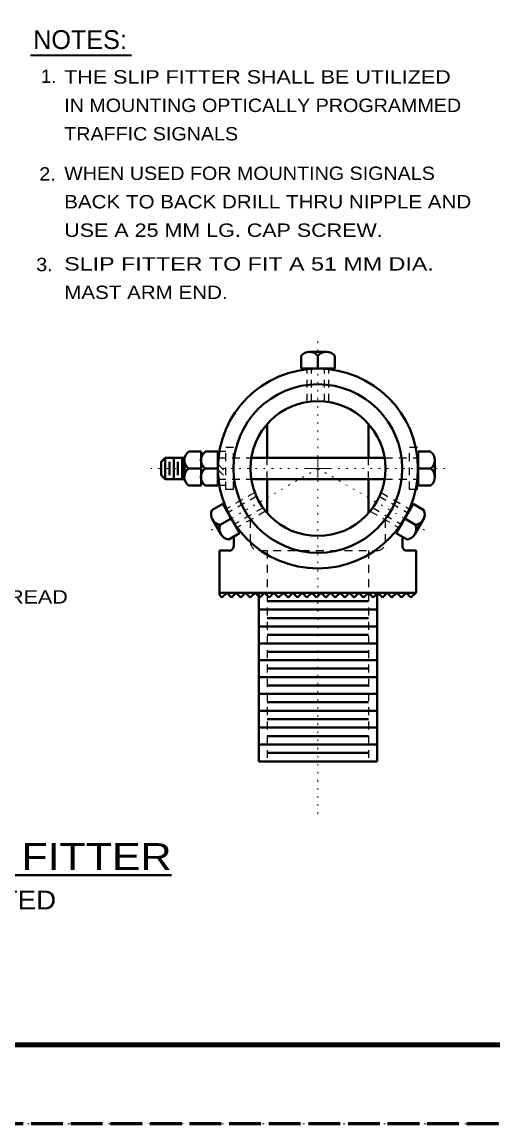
# Model space of a CAD drawing. Extents: x 312583 to 312854, y 144419 to 144597.
# Drawn here: x 312772.9 to 312799.7, y 144418.6 to 144481.2 of the extents above; entities that cross this region are included whole.
import ezdxf
from ezdxf.enums import TextEntityAlignment as Align

# ---------------------------------------------------------------- set-up
doc = ezdxf.new("R2010")
doc.units = 0
doc.header["$LTSCALE"] = 0.3
for name, pattern in [('DOTTED', [1.5, 0.3, -1.2]), ('LONG_DASHED', [7.5, 6, -1.5]), ('SHORT_DASHED', [2.7, 1.5, -1.2])]:
    doc.linetypes.add(name, pattern=pattern)
for name, color, linetype, lineweight in [('1', 7, 'Continuous', 40), ('2', 7, 'Continuous', 13), ('62', 7, 'DOTTED', 13), ('63', 7, 'LONG_DASHED', 60)]:
    doc.layers.add(name, color=color, linetype=linetype, lineweight=lineweight)

msp = doc.modelspace()

# ---------------------------------------------------------------- linework, layer by layer
at = {"layer": '1'}
for p, q in [((312788.779, 144462.2559), (312788.779, 144461.5429)), ((312790.2356, 144462.4935), (312789.239, 144462.4935)), ((312790.2203, 144462.4935), (312789.2466, 144462.4935)), ((312789.7373, 144462.2559), (312789.7373, 144461.5429)), ((312790.6956, 144462.2559), (312790.6956, 144461.5429)), ((312790.6956, 144461.5429), (312788.779, 144461.5429)), ((312786.8623, 144456.4675), (312786.8623, 144458.3842)), ((312792.6123, 144456.4675), (312792.6123, 144458.3842)), ((312782.385, 144456.8125), (312783.098, 144456.8125)), ((312783.098, 144454.8959), (312783.098, 144456.8125)), ((312783.3356, 144456.8125), (312784.0486, 144456.8125)), ((312784.0486, 144454.8959), (312784.0486, 144456.8125)), ((312796.1466, 144456.8125), (312795.4336, 144456.8125)), ((312795.4336, 144454.8959), (312795.4336, 144456.8125)), ((312781.0663, 144456.4675), (312782.1626, 144456.4675)), ((312781.3116, 144455.4785), (312781.3116, 144456.2299)), ((312781.5493, 144455.2409), (312781.5493, 144456.4675)), ((312781.787, 144455.4785), (312781.787, 144456.2299)), ((312782.0246, 144455.2409), (312782.0246, 144456.4675)), ((312782.155, 144455.3712), (312782.155, 144456.3449)), ((312783.098, 144455.3712), (312783.098, 144456.3449)), ((312785.9576, 144456.4675), (312793.5246, 144456.4675)), ((312796.3766, 144455.3559), (312796.3766, 144456.3525)), ((312796.3766, 144455.3712), (312796.3766, 144456.3449)), ((312782.385, 144455.8542), (312783.098, 144455.8542)), ((312783.3356, 144455.8542), (312784.0486, 144455.8542)), ((312796.1466, 144455.8542), (312795.4336, 144455.8542)), ((312781.0663, 144455.2409), (312782.1626, 144455.2409)), ((312782.385, 144454.8959), (312783.098, 144454.8959)), ((312783.3356, 144454.8959), (312784.0486, 144454.8959)), ((312785.9576, 144455.2409), (312793.5246, 144455.2409)), ((312786.8623, 144453.3165), (312786.8623, 144455.2409)), ((312792.6123, 144453.3165), (312792.6123, 144455.2409)), ((312796.1466, 144454.8959), (312795.4336, 144454.8959)), ((312783.7113, 144453.4775), (312784.3323, 144453.8379)), ((312784.3323, 144453.8379), (312785.2906, 144452.1742)), ((312794.1916, 144452.1742), (312795.15, 144453.8379)), ((312795.7633, 144453.4775), (312795.15, 144453.8379)), ((312783.742, 144452.9639), (312784.2403, 144452.0975)), ((312783.7496, 144452.9485), (312784.2403, 144452.1052)), ((312784.1943, 144452.6495), (312784.8076, 144453.0099)), ((312795.288, 144452.6495), (312794.667, 144453.0022)), ((312795.242, 144452.1052), (312795.7403, 144452.9715)), ((312795.2496, 144452.1205), (312795.7326, 144452.9639)), ((312784.6696, 144451.8215), (312785.2906, 144452.1742)), ((312794.805, 144451.8215), (312794.1916, 144452.1742)), ((312784.9533, 144451.4152), (312784.9533, 144451.9825)), ((312794.5443, 144451.4229), (312794.5443, 144451.9672)), ((312784.1406, 144451.1852), (312784.708, 144451.1852)), ((312795.311, 144451.1852), (312794.782, 144451.1852)), ((312784.1406, 144448.6629), (312784.2863, 144448.5172)), ((312784.5546, 144448.7855), (312784.2863, 144448.5172)), ((312784.5546, 144448.7855), (312784.823, 144448.5172)), ((312785.0913, 144448.7855), (312784.823, 144448.5172)), ((312785.0913, 144448.7855), (312785.3596, 144448.5172)), ((312785.628, 144448.7855), (312785.3596, 144448.5172)), ((312785.628, 144448.7855), (312785.8963, 144448.5172)), ((312786.1646, 144448.7855), (312785.8963, 144448.5172)), ((312786.1646, 144448.7855), (312786.433, 144448.5172)), ((312786.7013, 144448.7855), (312786.433, 144448.5172)), ((312786.7013, 144448.7855), (312786.9696, 144448.5172)), ((312787.238, 144448.7855), (312786.9696, 144448.5172)), ((312787.238, 144448.7855), (312787.5063, 144448.5172)), ((312787.7746, 144448.7855), (312787.5063, 144448.5172)), ((312787.7746, 144448.7855), (312788.043, 144448.5172)), ((312788.3113, 144448.7855), (312788.043, 144448.5172)), ((312788.3113, 144448.7855), (312788.5796, 144448.5172)), ((312788.848, 144448.7855), (312788.5796, 144448.5172)), ((312788.848, 144448.7855), (312789.1163, 144448.5172)), ((312789.3846, 144448.7855), (312789.1163, 144448.5172)), ((312789.3846, 144448.7855), (312789.653, 144448.5172)), ((312789.9213, 144448.7855), (312789.653, 144448.5172)), ((312789.9213, 144448.7855), (312790.1896, 144448.5172)), ((312790.458, 144448.7855), (312790.1896, 144448.5172)), ((312790.458, 144448.7855), (312790.7263, 144448.5172)), ((312790.9946, 144448.7855), (312790.7263, 144448.5172)), ((312790.9946, 144448.7855), (312791.263, 144448.5172)), ((312791.5313, 144448.7855), (312791.263, 144448.5172)), ((312791.5313, 144448.7855), (312791.7996, 144448.5172)), ((312792.068, 144448.7855), (312791.7996, 144448.5172)), ((312792.068, 144448.7855), (312792.3363, 144448.5172)), ((312792.6046, 144448.7855), (312792.3363, 144448.5172)), ((312792.6046, 144448.7855), (312792.873, 144448.5172)), ((312793.1413, 144448.7855), (312792.873, 144448.5172)), ((312793.1413, 144448.7855), (312793.4096, 144448.5172)), ((312793.678, 144448.7855), (312793.4096, 144448.5172)), ((312793.678, 144448.7855), (312793.9463, 144448.5172)), ((312794.2146, 144448.7855), (312793.9463, 144448.5172)), ((312794.2146, 144448.7855), (312794.483, 144448.5172)), ((312794.7513, 144448.7855), (312794.483, 144448.5172)), ((312794.7513, 144448.7855), (312795.0196, 144448.5172)), ((312795.311, 144448.8085), (312795.0196, 144448.5172))]:
    msp.add_line(p, q, dxfattribs=at)
at = {"layer": '1', "linetype": 'SHORT_DASHED', "lineweight": 25}
for p, q in [((312789.124, 144459.6415), (312789.124, 144461.5352)), ((312789.3693, 144459.6415), (312789.3693, 144461.5352)), ((312790.113, 144459.6415), (312790.113, 144461.5352)), ((312790.3506, 144459.6415), (312790.3506, 144461.5352)), ((312784.501, 144456.8125), (312784.0486, 144456.8125)), ((312784.501, 144454.6582), (312784.501, 144457.0502)), ((312784.9456, 144457.0502), (312784.501, 144457.0502)), ((312784.9456, 144454.6582), (312784.9456, 144457.0502)), ((312794.943, 144454.6582), (312794.943, 144457.0502)), ((312795.3876, 144454.6582), (312795.3876, 144457.0502)), ((312784.0486, 144456.4675), (312785.9576, 144456.4675)), ((312784.0486, 144456.0995), (312784.501, 144455.6472)), ((312786.8623, 144455.2409), (312786.8623, 144456.4675)), ((312792.6123, 144455.2409), (312792.6123, 144456.4675)), ((312793.5246, 144456.4675), (312795.4183, 144456.4675)), ((312784.0486, 144455.8005), (312784.501, 144455.3482)), ((312784.0486, 144455.2409), (312785.9576, 144455.2409)), ((312784.501, 144454.8959), (312784.0486, 144454.8959)), ((312784.9456, 144454.6582), (312784.501, 144454.6582)), ((312793.5246, 144455.2409), (312795.4183, 144455.2409)), ((312795.2496, 144454.6582), (312794.943, 144454.6582)), ((312795.3876, 144454.6582), (312795.3033, 144454.6582)), ((312786.1493, 144454.4895), (312784.5086, 144453.5465)), ((312786.272, 144454.2825), (312784.6313, 144453.3395)), ((312793.2103, 144454.2825), (312794.8433, 144453.3395)), ((312793.3253, 144454.4895), (312794.966, 144453.5465)), ((312786.6476, 144453.6309), (312785.007, 144452.6879)), ((312786.7626, 144453.4239), (312785.1296, 144452.4809)), ((312792.712, 144453.4239), (312794.3526, 144452.4809)), ((312792.8346, 144453.6309), (312794.4676, 144452.6879)), ((312785.904, 144451.6605), (312785.904, 144452.9792)), ((312793.5706, 144451.6605), (312793.5706, 144452.9792))]:
    msp.add_line(p, q, dxfattribs=at)
at = {"layer": '1', "linetype": 'DOTTED', "lineweight": 13}
for q in [(312783.5886, 144452.3045), (312796.093, 144452.1819)]:
    msp.add_line((312789.7373, 144455.8542), q, dxfattribs=at)
at = {"layer": '1', "lineweight": 158}
msp.add_line((312616.5, 144423.0846), (312849, 144423.0846), dxfattribs=at)
at = {"layer": '1', "linetype": 'SHORT_DASHED', "lineweight": 25}
msp.add_lwpolyline([(312795.3876, 144457.0502), (312795.2956, 144457.0502), (312794.943, 144457.0502)], dxfattribs=at)
at = {"layer": '1'}
for points in [[(312780.8286, 144455.4785), (312781.0663, 144455.2409), (312781.0663, 144456.4675)], [(312780.8286, 144455.4785), (312780.8286, 144456.2299), (312781.0663, 144456.4675)]]:
    msp.add_lwpolyline(points, dxfattribs=at)
for radius in [5.681, 4.7917, 3.8333]:
    msp.add_circle((312789.7373, 144455.8504), radius, dxfattribs=at)
for centre, radius, start, end in [((312789.2581, 144461.8858), 0.6054, 37.67771, 142.32229), ((312790.2165, 144461.8858), 0.6054, 37.67771, 142.32229), ((312782.755, 144456.3295), 0.6054, 127.67771, 232.32229), ((312783.7018, 144456.3295), 0.6054, 127.67771, 232.32229), ((312795.7728, 144456.3295), 0.6054, 307.67771, 52.32229), ((312782.755, 144455.3712), 0.6054, 127.67771, 232.32229), ((312783.7018, 144455.3712), 0.6054, 127.67771, 232.32229), ((312795.7728, 144455.3712), 0.6054, 307.67771, 52.32229), ((312784.2709, 144453.2476), 0.6054, 157.67771, 262.32229), ((312795.2037, 144453.2476), 0.6054, 277.67771, 22.32229), ((312784.75, 144452.4177), 0.6054, 157.67771, 262.32229), ((312794.7246, 144452.4177), 0.6054, 277.67771, 22.32229), ((312784.7084, 144451.4209), 0.2396, 270, 358.87648), ((312794.7819, 144451.4209), 0.2396, 173.62063, 270)]:
    msp.add_arc(centre, radius, start, end, dxfattribs=at)
at = {"layer": '1', "linetype": 'SHORT_DASHED', "lineweight": 25}
for centre, start, end in [((312786.3831, 144451.6605), 180, 270), ((312793.0915, 144451.6605), 270, 0)]:
    msp.add_arc(centre, 0.4792, start, end, dxfattribs=at)
at = {"layer": '2', "lineweight": 35}
msp.add_line((312773.41, 144479.352), (312779.1524, 144479.352), dxfattribs=at)
at = {"layer": '2', "linetype": 'DOTTED'}
for p, q in [((312789.7373, 144457.0042), (312789.7373, 144463.4212)), ((312788.5873, 144455.8542), (312780.2536, 144455.8542)), ((312790.8873, 144455.8542), (312797.2813, 144455.8542)), ((312789.7373, 144454.7042), (312789.7373, 144436.0512))]:
    msp.add_line(p, q, dxfattribs=at)
at = {"layer": '2'}
for q in [(312789.7373, 144456.6209), (312788.9706, 144455.8542), (312790.504, 144455.8542), (312789.7373, 144455.0875)]:
    msp.add_line((312789.7373, 144455.8542), q, dxfattribs=at)
at = {"layer": '2', "lineweight": 40}
for p, q in [((312784.1406, 144451.1852), (312784.1406, 144448.6629)), ((312795.311, 144451.1852), (312795.311, 144448.8085)), ((312784.1406, 144448.7855), (312795.311, 144448.7855)), ((312786.387, 144448.7855), (312786.387, 144439.2022)), ((312793.0953, 144448.7855), (312793.0953, 144439.2022)), ((312786.387, 144447.8272), (312793.0953, 144447.8272)), ((312786.8623, 144448.3102), (312792.6123, 144448.3102)), ((312786.8623, 144447.3519), (312792.6123, 144447.3519)), ((312786.387, 144446.8689), (312793.0953, 144446.8689)), ((312786.387, 144445.9105), (312793.0953, 144445.9105)), ((312786.8623, 144446.3935), (312792.6123, 144446.3935)), ((312786.8623, 144445.4352), (312792.6123, 144445.4352)), ((312786.387, 144444.9522), (312793.0953, 144444.9522)), ((312786.387, 144443.9939), (312793.0953, 144443.9939)), ((312786.8623, 144444.4769), (312792.6123, 144444.4769)), ((312786.8623, 144443.5185), (312792.6123, 144443.5185)), ((312786.387, 144443.0355), (312793.0953, 144443.0355)), ((312786.8623, 144442.5602), (312792.6123, 144442.5602)), ((312786.387, 144442.0772), (312793.0953, 144442.0772)), ((312786.8623, 144441.6019), (312792.6123, 144441.6019)), ((312786.387, 144441.1189), (312793.0953, 144441.1189)), ((312786.8623, 144440.6435), (312792.6123, 144440.6435)), ((312786.387, 144440.1605), (312793.0953, 144440.1605)), ((312786.8623, 144439.6852), (312792.6123, 144439.6852)), ((312786.387, 144439.2022), (312793.0953, 144439.2022)), ((312738.5429, 144432.7279), (312781.4178, 144432.7279))]:
    msp.add_line(p, q, dxfattribs=at)
at = {"layer": '2', "linetype": 'SHORT_DASHED', "lineweight": 25}
for p, q in [((312786.387, 144451.1852), (312793.0953, 144451.1852)), ((312786.8623, 144451.1852), (312786.8623, 144439.2022)), ((312792.6123, 144451.1852), (312792.6123, 144439.2022))]:
    msp.add_line(p, q, dxfattribs=at)
at = {"layer": '62'}
msp.add_lwpolyline([(312601.2, 144418.5846), (312853.5, 144418.5846), (312853.5, 144596.7846)], dxfattribs=at)
at = {"layer": '63'}
msp.add_line((312851.75, 144418.5846), (312583.526, 144418.5846), dxfattribs=at)

# ---------------------------------------------------------------- texts
at = {"layer": '2'}
msp.add_text('NOTES:', height=1.07, dxfattribs=at).set_placement((312776.2266, 144479.7052), align=Align.CENTER)
for s, width, p in [('1.   ', 1.05, (312774.0007, 144477.7764)), ('THE SLIP FITTER SHALL BE UTILIZED', 1.2, (312775.3267, 144477.741)), ('IN MOUNTING OPTICALLY PROGRAMMED', 1.1, (312775.3267, 144476.1233)), ('TRAFFIC SIGNALS', 1.1, (312775.3267, 144474.5057)), ('2.  ', 1.1, (312773.9128, 144472.2239)), ('WHEN USED FOR MOUNTING SIGNALS', 1.1, (312775.3267, 144472.2593)), ('BACK TO BACK DRILL THRU NIPPLE AND', 1.15, (312775.3267, 144470.6417)), ('USE A 25 MM LG. CAP SCREW.', 1.2, (312775.3267, 144469.024)), ('3.  ', 1.1, (312773.7357, 144467.0718)), ('SLIP FITTER TO FIT A 51 MM DIA.', 1.3, (312775.3267, 144467.1073)), ('MAST ARM END.', 1.15, (312775.3267, 144465.4897)), ('47.80 MM PIPE THREAD', 1.2, (312761.6353, 144448.1752))]:
    msp.add_text(s, height=0.76, dxfattribs=dict(at, width=width)).set_placement(p)
for s, height, width, p in [('ALTERNATE MAST ARM SLIP FITTER', 1.52, 1.2, (312759.8793, 144433.0327)), ('SAME AS ABOVE EXCEPT WHERE NOTED', 1.07, 1.1, (312758.9496, 144430.784))]:
    msp.add_text(s, height=height, dxfattribs=dict(at, width=width)).set_placement(p, align=Align.CENTER)

doc.saveas('drawing.dxf')
